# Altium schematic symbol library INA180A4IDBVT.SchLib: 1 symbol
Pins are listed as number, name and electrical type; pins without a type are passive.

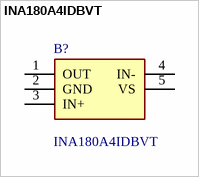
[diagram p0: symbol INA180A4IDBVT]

## INA180A4IDBVT
designator B?
26V, 350kHz Bandwidth, Low- or High-Side Voltage Output Current Sense Amplifier; Manufacturer_Name: Texas Instruments; Geometry.Height: 1.45mm
footprint SOT95P280X145-5N
pins: 1 OUT, 2 GND, 3 IN+, 4 IN-, 5 VS (power)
